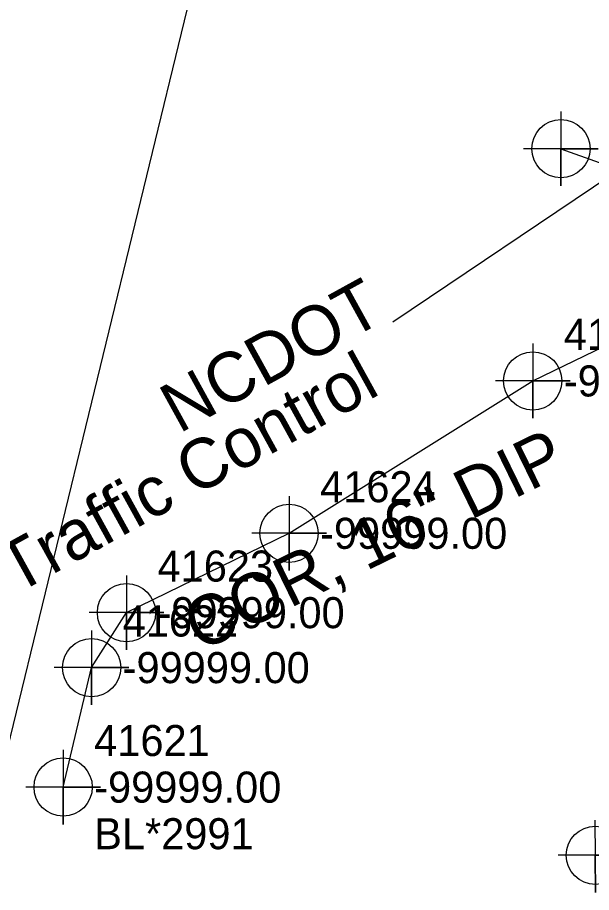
# Model space of a CAD drawing. Extents: x 2083698 to 2094313, y 743246 to 752873.
# Drawn here: x 2093556.1 to 2093602.3, y 743723.6 to 743794.1 of the extents above; entities that cross this region are included whole.
import ezdxf

# ---------------------------------------------------------------- set-up
doc = ezdxf.new("R2010")
doc.units = 0
for name, color, linetype in [('COGO Default Point Number', 7, 'Continuous'), ('Exist Property Iron Pin Text', 7, 'Continuous'), ('Exist Property Line', 7, 'Continuous'), ('Exist Right of Way Line', 7, 'Continuous'), ('Exist Right of Way Line Text', 7, 'Continuous'), ('Exist Right of Way Width CELL', 7, 'Continuous'), ('Exist Utilities Power UG Cable SUE LOS B', 7, 'Continuous'), ('Exist Utilities Power UG Cable SUE LOS B Leader', 7, 'Continuous'), ('Exist Utilities Power UG Cable SUE LOS B Text', 7, 'Continuous'), ('Exist Utilities Telephone UG Conduit SUE LOS D', 7, 'Continuous'), ('Exist Utilities Water UG Line SUE LOS B', 7, 'Continuous'), ('Exist Utilities Water UG Line SUE LOS B Text', 7, 'Continuous')]:
    doc.layers.add(name, color=color, linetype=linetype)

msp = doc.modelspace()

# ---------------------------------------------------------------- linework, layer by layer
at = {"layer": 'COGO Default Point Number'}
for points in [[(2093597.536, 743767.808), (2093597.536, 743761.808), (2093597.536, 743764.808), (2093600.536, 743764.808), (2093594.536, 743764.808)], [(2093577.924, 743755.544), (2093577.924, 743749.544), (2093577.924, 743752.544), (2093580.924, 743752.544), (2093574.924, 743752.544)], [(2093564.841, 743749.156), (2093564.841, 743743.156), (2093564.841, 743746.156), (2093567.841, 743746.156), (2093561.841, 743746.156)], [(2093562.033, 743744.733), (2093562.033, 743738.733), (2093562.033, 743741.733), (2093565.033, 743741.733), (2093559.033, 743741.733)], [(2093559.744, 743735.115), (2093559.744, 743729.115), (2093559.744, 743732.115), (2093562.744, 743732.115), (2093556.744, 743732.115)]]:
    msp.add_lwpolyline(points, dxfattribs=at)
for centre in [(2093597.536, 743764.808), (2093577.924, 743752.544), (2093564.841, 743746.156), (2093562.033, 743741.733), (2093559.744, 743732.115)]:
    msp.add_circle(centre, 2.344, dxfattribs=at)
at = {"layer": 'Exist Property Iron Pin Text'}
msp.add_lwpolyline([(2093599.8, 743786.501), (2093599.8, 743780.501), (2093599.8, 743783.501), (2093602.8, 743783.501), (2093596.8, 743783.501)], dxfattribs=at)
msp.add_circle((2093599.8, 743783.501), 2.344, dxfattribs=at)
at = {"layer": 'Exist Right of Way Line Text'}
msp.add_lwpolyline([(2093602.539, 743729.448), (2093602.572, 743723.633), (2093602.555, 743726.633), (2093605.572, 743726.633), (2093599.572, 743726.633)], dxfattribs=at)
msp.add_circle((2093602.572, 743726.633), 2.344, dxfattribs=at)
at = {"layer": 'Exist Utilities Power UG Cable SUE LOS B'}
msp.add_lwpolyline([(2093599.8, 743783.501), (2093606.326, 743781.146), (2093615.684, 743775.129), (2093619.852, 743771.315)], dxfattribs=at)
at = {"layer": 'Exist Utilities Power UG Cable SUE LOS B Leader'}
msp.add_line((2093586.287, 743769.566), (2093603.895, 743781.424), dxfattribs=at)
at = {"layer": 'Exist Utilities Telephone UG Conduit SUE LOS D'}
msp.add_lwpolyline([(2093729.858, 746559.978), (2093729.858, 746485.514), (2093728.609, 746416.156), (2093711.624, 746127.005), (2093702.367, 745955.823), (2093693.11, 745784.641), (2093668.684, 745395.409), (2093654.742, 745161.512), (2093649.119, 745054.601), (2093640.354, 744903.623), (2093631.766, 744751.077), (2093623.847, 744627.433), (2093615.928, 744503.789), (2093603.659, 744373.896), (2093590.721, 744165.443), (2093582.979, 744085.275), (2093575.237, 744005.107), (2093571.649, 743852.762), (2093573.497, 743810.293), (2093555.014, 743734.283)], dxfattribs=at)
at = {"layer": 'Exist Utilities Water UG Line SUE LOS B'}
msp.add_lwpolyline([(2093559.744, 743732.115), (2093562.033, 743741.733), (2093564.841, 743746.156), (2093577.924, 743752.544), (2093597.536, 743764.808), (2093612.448, 743772.039)], dxfattribs=at)

# ---------------------------------------------------------------- texts
at = {"layer": 'Exist Property Line'}
for p in [(2093600.036, 743763.558), (2093580.424, 743751.294), (2093567.341, 743744.906), (2093564.533, 743740.483), (2093562.244, 743730.865)]:
    msp.add_text('-99999.00', height=2.5, dxfattribs=at).set_placement(p)
at = {"layer": 'Exist Right of Way Line'}
for s, p in [('41625', (2093600.036, 743767.308)), ('41624', (2093580.424, 743755.044)), ('41623', (2093567.341, 743748.656)), ('41622', (2093564.533, 743744.233)), ('41621', (2093562.244, 743734.615))]:
    msp.add_text(s, height=2.5, dxfattribs=at).set_placement(p)
at = {"layer": 'Exist Right of Way Width CELL'}
msp.add_text('BL*2991', height=2.5, dxfattribs=at).set_placement((2093562.244, 743727.115))
at = {"layer": 'Exist Utilities Power UG Cable SUE LOS B Text'}
for s, p in [('NCDOT ', (2093569.076, 743760.54)), ('Traffic Control', (2093555.96, 743747.599))]:
    msp.add_text(s, height=4, rotation=28.84351, dxfattribs=at).set_placement(p)
at = {"layer": 'Exist Utilities Water UG Line SUE LOS B Text'}
msp.add_text('COR, 16" DIP', height=4, rotation=26.02474, dxfattribs=at).set_placement((2093570.758, 743742.966))

doc.saveas('drawing.dxf')
